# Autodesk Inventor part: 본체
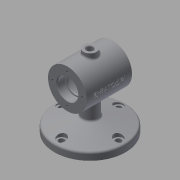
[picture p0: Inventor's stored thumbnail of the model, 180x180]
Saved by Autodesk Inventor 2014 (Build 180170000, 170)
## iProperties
Created: 2018-12
Part Number: 본체
Material: Generic
Document SubType Name: Modeling
Designer: kh
Density: 1 g/cm^3
Appearance: Default
Author: kh
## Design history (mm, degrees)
sketch "Sketch1"
  geometry: C1 r 55 at (0, 0); 1 further point
  constraints: 1 centre point, 1 coincident
  dimensions: "d0" = 110 diameter of C1
extrude "Extrusion1" new body sketch "Sketch1" distance "d1" = 11; taper "d2" = 0 deg
workplane "Work Plane1"
workplane "Work Plane2"
workplane "Work Plane3"
workplane "Work Plane5"
workplane "Work Plane6"
workplane "Work Plane7"
sketch "Sketch14"
  geometry: L1 (-47.043, 75)-(44.509, 75); L2 (-55, 0)-(55, 0) reference; L3 (-35, 105)-(35, 105); L4 (35, 105)-(35, 75); L5 (-35, 75)-(-35, 105); L6 (0, 0)-(0, 125.923); L7 (-35, 75)-(-23, 75); L8 (-23, 75)-(-23, 90.7); L9 (-23.3, 91)-(-35, 91); L10 (-35, 91)-(-35, 75); L11 (-23, 75)-(-20, 75); L12 (-20, 75)-(-20, 89); L13 (-20, 89)-(-23, 89); L14 (-23, 89)-(-23, 75); L15 (-20, 75)-(20, 75); L16 (20, 75)-(20, 97); L17 (17, 100)-(-17, 100); L18 (-20, 97)-(-20, 75); L19 (20, 75)-(23, 75); L20 (23, 75)-(23, 89); L21 (23, 89)-(20, 89); L22 (20, 89)-(20, 75); L23 (23, 75)-(35, 75); L24 (35, 75)-(35, 91); L25 (35, 91)-(23.3, 91); L26 (23, 90.7)-(23, 75); A1 r 3 centre (-17, 97) between (-17, 100) and (-20, 97); A2 r 3 centre (17, 97) between (20, 97) and (17, 100); A3 r 0.3 centre (-23.3, 90.7) between (-23, 90.7) and (-23.3, 91); A4 r 0.3 centre (23.3, 90.7) between (23.3, 91) and (23, 90.7)
  constraints: 50 end point, 12 parallel, 8 point on circle, 8 tangent, 7 horizontal, 6 perpendicular, 4 centre point, 3 point on line, 2 equal radius, 2 other
  dimensions: "d83" = 75 distance between parallel lines of L2 L1; "d84" = 70 distance between parallel lines of L4 L5; "d85" = 60 diameter of L3 L1; "d86" = 32 diameter of L9 L1; "d87" = 28 diameter of L13 L1; "d88" = 50 diameter of L17 L1; "d89" = 28 diameter of L21 L1; "d90" = 32 diameter of L25 L1; "d91" = 12 distance between parallel lines of L4 L20; "d92" = 12 distance between parallel lines of L5 L14; "d93" = 40 distance between parallel lines of L22 L18; "d94" = 3 radius of A1; "d95" = 0.3 radius of A3
revolve "Revolution3" sketch "Sketch14" stored, may be unused: angle "d96" = 90 deg
sketch "Sketch15"
  geometry: C1 r 12 at (0, 0); 1 further point
  constraints: 1 centre point, 1 coincident
  dimensions: "d97" = 24 diameter of C1
extrude "Extrusion5" join sketch "Sketch15" stored distance "d98" = 10; taper "d99" = 0 deg
sketch "Sketch16"
  geometry: L1 (55, 11)-(-55, 11) reference; L2 (-55, 0)-(-55, 11) reference; L3 (-12, 11)-(-12, 45) reference; L4 (-55, 11)-(-6.532, 23.987); L5 (-6.532, 23.987)-(-6.532, 11); L6 (-55, 11)-(-6.532, 11); L7 (0, 0)-(0, 37.906)
  constraints: 8 end point, 2 perpendicular, 1 collinear, 1 point on line
  dimensions: "d100" = 75 deg angle of L2 L4; "d101" = 12.98704 distance of L4.end L5.end
revolve "Revolution4" sketch "Sketch16" stored, may be unused: angle "d102" = 90 deg
sketch "Sketch17" dims "d103" = 88
  geometry: L1 (0, 0)-(0, 44); 2 further points
  constraints: 2 coincident, 2 end point, 1 vertical, 1 vertical alignment, 2 other
hole "Hole4" sketch "Sketch17" at (0, 44) diameter "d104" = 9; stored, may be unused: countersink angle "d108" = 90 deg, drill point angle "d110" = 0 deg; dims "d105" = 6, "d106" = 4, "d107" = 2, "d109" = 10
sketch "Sketch18"
  geometry: C1 r 4.5 at (0, 0) reference; C2 r 7 at (0, 0); 1 further point
  constraints: 1 centre point, 1 coincident
  dimensions: "d111" = 14 diameter of C2
extrude "Extrusion6" cut sketch "Sketch18" distance "d112" = 10; taper "d113" = 0 deg
pattern_circular "Circular Pattern3" dims angle "d115" = 360 deg
sketch "Sketch19" dims "d117" = 46
  geometry: L1 (0, 0)-(0, 23); C1 r 14 at (0, 0) reference; 2 further points
  constraints: 2 coincident, 2 end point, 1 vertical, 1 vertical alignment, 2 other
hole "Hole5" sketch "Sketch19" at (0, 23) diameter "d118" = 3.459; stored, may be unused: countersink angle "d122" = 90 deg, drill point angle "d124" = 118 deg; dims "d119" = 8, "d120" = 4, "d121" = 2, "d123" = 10
pattern_circular "Circular Pattern4" dims angle "d126" = 360 deg
workplane "Work Plane8"
mirror "Mirror2"
chamfer "Chamfer2" distance "d129" = 1; stored, may be unused: second distance "d130" = 2, angle "d131" = 45 deg
workplane "Work Plane9"
sketch "Sketch20"
  geometry: C1 r 10 at (0, 0); 1 further point
  constraints: 1 centre point, 1 coincident
  dimensions: "d133" = 20 diameter of C1
extrude "Extrusion7" join sketch "Sketch20" stored distance "d134" = 10; taper "d135" = 0 deg
hole "Hole6" diameter "d138" = 10; stored, may be unused: countersink angle "d142" = 90 deg, drill point angle "d144" = 118 deg; dims "d136" = 10, "d137" = 10, "d139" = 8, "d140" = 4, "d141" = 2, "d143" = 25
chamfer "Chamfer3" distance "d145" = 1; stored, may be unused: second distance "d146" = 2, angle "d147" = 45 deg
fillet "Fillet4" dims "d148" = 3
workplane "Work Plane10"
sketch "Sketch21" dims "d1" = 11, "d2" = 0, "d136" = 10, "d137" = 10
  geometry: L1 (-35, 105)-(35, 105) reference; L2 (-35, 45)-(-35, 105) reference; L3 (-24.887, 78.602)-(24.887, 78.602); L4 (24.887, 78.602)-(24.887, 71.398); L5 (24.887, 71.398)-(-24.887, 71.398); L6 (-24.887, 71.398)-(-24.887, 78.602); L7 (0, 105)-(0, 0); L8 (-35, 75)-(0, 75); L9 (24.887, 71.398)-(-24.887, 78.602); 1 further point
  constraints: 6 end point, 3 midpoint, 1 coincident, 1 parallel, 1 perpendicular, 1 point on line, 2 other
  dimensions: "d150" = 30 distance between parallel lines of L1 L8
emboss "Emboss2" sketch "Sketch21" dims "d151" = 0.5, "d152" = 0
fillet "Fillet5" dims "d153" = 3
body "Solid1"
node "Projected Loop5"
other parameters: "d3" = 0, "d13" = 75, "d40" = 112, "d74" = 71.5, "d77" = 0, "d82" = 0, "d128" = 0, "d132" = 112, "d149" = 58.75
